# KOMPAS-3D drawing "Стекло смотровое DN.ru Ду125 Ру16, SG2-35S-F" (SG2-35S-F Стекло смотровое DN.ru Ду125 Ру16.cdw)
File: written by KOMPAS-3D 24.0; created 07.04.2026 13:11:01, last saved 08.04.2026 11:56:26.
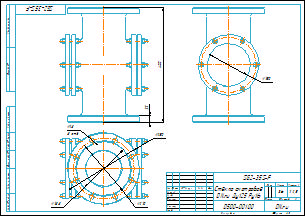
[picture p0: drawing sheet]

Document properties: Автор: Main; Форматы листов документа: A3; Полное имя файла: SG2-35S-F Стекло смотровое DN.ru Ду125 Ру16.m3d; Масса: 36; Наименование: Стекло смотровое DN.ru Ду125 Ру16; Количество листов документа: 1; Примечание: D500-00100

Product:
- Body: Тело 1  | qty 1
    Масса: 38.267558
- Part/product: Стекло смотровое DN.ru Ду125 Ру16  | designation SG2-35S-F
    Масса: 36
    Раздел спецификации: Прочие изделия
    Примечание: D500-00100

Referenced files in D:\DN.ru Аутсерс\Стекло смотровое DN.ru\Стекло смотровое DN.ru SG2-34G-F тип В ГОСТ 21836-2021 Ду100 Ру16, углеродистая сталь, фланцевое\: SG2-34G-F тип ВСтекло смотровое DN.ru Ду100 Ру16.cdw
Referenced files in D:\DN.ru Аутсерс\Стекло смотровое DN.ru\SG2-35S-F Стекло смотровое DN.ru Ду125 Ру16\: SG2-35S-F Стекло смотровое DN.ru Ду125 Ру16.m3d
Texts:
  Стекло смотровое
  DN.ru Ду125 Ру16
  SG2-35S-F
  Стекло смотровое DN.ru Ду125 Ру16
  SG2-35S-F Стекло смотровое DN.ru Ду125 Ру16
Dimensions and other numbers on the sheet: 1:2,5; 0; 1; 2; 36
